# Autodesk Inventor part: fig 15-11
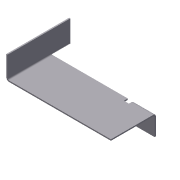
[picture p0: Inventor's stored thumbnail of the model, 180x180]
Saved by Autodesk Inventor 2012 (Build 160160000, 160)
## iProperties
Shininess: 77.0
Angle Display Precision: 2
Document Length Units: 11269
Document Angle Units: 11279
Document Time Units: 11290
Document Mass Units: 11283
Document Length Units Precision: 3
Document Angle Units Precision: 2
Created: 2002-04
Part Number: fig 15-11
Material: Aluminum-6061
Document SubType Name: Sheet Metal
Density: 1 g/cm^3
Sheet Metal Rule: Default
Density: 0.0
Volumn: 0.0
Area: 0.0
PropertySet Name: Model Information
Control State: 0
Master: False
Checked Out: False
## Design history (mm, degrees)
node "Face1"
  sketch "Sketch1"
    geometry: L1 (-49.559, 19.574)-(-49.559, -30.426); L2 (-49.559, -30.426)-(50.441, -30.426); L3 (50.441, -30.426)-(50.441, 19.574); L4 (50.441, 19.574)-(32.941, 19.574); L5 (32.941, 19.574)-(32.941, 4.574); L6 (32.941, 4.574)-(-32.059, 4.574); L7 (-32.059, 4.574)-(-32.059, 19.574); L8 (-32.059, 19.574)-(-49.559, 19.574)
    constraints: 16 end point, 6 parallel, 2 equal length, 1 perpendicular, 1 vertical
    dimensions: "d0" = 100 distance of L1.end L2.end; "d1" = 65 distance of L5.end L6.end; "d2" = 15 distance of L6.end L7.end; "d3" = 50 distance of L1.start L1.end
sketch "Sketch2"
  geometry: L1 (100, 0)-(0, 0) reference; L2 (17.5, 50)-(17.5, 35) reference; L3 (82.5, 50)-(82.5, 0)
  constraints: 2 end point, 1 parallel, 1 point on line
sketch "Sketch3"
  geometry: L1 (81.369, -50)-(0, -50) reference; L2 (17.5, 0)-(17.5, -50)
  constraints: 2 end point, 1 perpendicular, 1 point on line
feature "Fold2" sketch "Sketch3" dims "d8" = 1 (= BendRadius), "d9" = 90 deg, "d10" = 1 (= BendRadius), "d14" = 1 (= BendReliefWidth), "d15" = 0.5 (= BendReliefDepth), "d16" = 2 (= MinimumRemnant), "SeamGap" = 0.01, "Thickness" = 1
sketch "Sketch4"
  geometry: L1 (17.5, 0)-(17.5, -50) reference; L2 (-63.869, -15)-(0, -15) reference; L3 (0, -15)-(17.5, -15)
  constraints: 2 end point, 1 collinear, 1 point on line
feature "Fold3" sketch "Sketch4" dims "d11" = 1 (= BendRadius), "d12" = 90 deg, "d13" = 1 (= BendRadius), "d17" = 4, "d18" = 2, "d19" = 2 (= MinimumRemnant), "SeamGap" = 0.01, "Thickness" = 1
body "Solid1"
face "Plate1" dims "Thickness" = 1
other parameters: "BendRadius" = 1 (= Thickness), "BendReliefWidth" = 1 (= Thickness), "BendReliefDepth" = 0.5 (= 0.5 x Thickness), "CornerReliefSize" = 4 (= 4 x Thickness), "MinimumRemnant" = 2 (= 2 x Thickness), "TransitionRadius" = 1 (= BendRadius), "d4" = 1 (= BendRadius), "JacobiRadiusSize" = 1 (= Thickness), "GapSize" = 1 (= Thickness)
